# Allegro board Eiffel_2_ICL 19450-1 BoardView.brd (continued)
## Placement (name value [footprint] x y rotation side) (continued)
NOREF#32  -  []  30.94 34.64 90 top
NOREF#33  -  []  176.95 38.55 0 top
NOREF#34  -  []  49.26 27.53 0 top
NOREF#35  -  []  177.55 54.59 90 top
NOREF#36  -  []  225.13 85.49 0 top
NOREF#37  -  [unnamed#2]  3.95 4.39 0 top
NOREF#38  -  []  48.05 24.21 0 top
NOREF#39  -  []  191.47 24.44 0 top
NOREF#40  -  []  181.37 48.8 0 top
NOREF#41  -  []  30.84 37.54 90 top
NOREF#42  -  []  49.95 26.35 0 top
NOREF#43  -  []  169.5 24.9 0 top
NOREF#44  -  []  25.99 59.56 0 top
NOREF#45  -  []  50.6 26.35 90 top
NOREF#46  -  []  229.62 98.92 90 top
NOREF#47  -  []  0 0 0 top
NOREF#48  -  []  186.84 37.95 0 top
NOREF#49  -  []  42.34 37.54 90 top
NOREF#50  *  [unnamed#2]  254.08 109.13 0 top
NOREF#51  -  []  177.55 54.59 90 top
NOREF#52  -  []  176.95 38.55 90 top
NOREF#53  -  []  186.84 37.95 90 top
NOREF#54  -  [unnamed#2]  161.82 65.49 0 top
NOREF#55  -  []  202.97 100.4 0 top
NOREF#56  -  [unnamed#2]  199.27 65.49 0 top
NOREF#57  -  []  49.39 23.54 90 top
NOREF#58  -  []  32.34 39.04 90 top
NOREF#59  -  [unnamed#2]  260.04 100.77 0 top
NOREF#60  -  []  30.84 40.04 0 top
NOREF#61  -  []  176.95 47.79 0 top
NOREF#62  -  []  144.17 28.29 90 top
NOREF#63  -  []  236.87 79.8 90 top
NOREF#64  -  []  0 0 0 top
NOREF#65  -  []  181.37 48.8 90 top
NOREF#66  -  []  178.9 63.83 0 top
NOREF#67  -  []  42.34 40.04 0 top
NOREF#68  -  []  179.5 63.83 90 top
NOREF#69  -  []  51.04 89.5 0 top
NOREF#70  -  []  30.94 34.64 90 top
NOREF#71  -  []  186.84 63.83 0 top
NOREF#72  -  [unnamed#2]  6.13 110.79 0 top
NOREF#73  *  [unnamed#2]  15.9 110.28 0 top
NOREF#74  -  []  213 82.14 0 top
NOREF#75  -  []  179.5 63.83 90 top
NOREF#76  -  []  178.9 59.06 0 top
NOREF#77  -  []  42.44 34.64 90 top
NOREF#78  *  [unnamed#2]  101.6 3.47 0 top
NOREF#79  -  []  37.49 49.55 90 top
NOREF#80  -  []  193.87 23.8 90 top
NOREF#81  -  []  233.4 4.81 90 top
NOREF#82  -  []  174.41 33.37 0 top
NOREF#83  -  []  144.86 28.97 0 top
NOREF#84  *  [unnamed#2]  72.04 97.13 0 top
NOREF#85  -  []  177.55 37.95 90 top
NOREF#86  -  []  186.84 63.83 0 top
NOREF#87  -  []  202.28 99.23 0 top
NOREF#88  *  [unnamed#2]  258.59 96.1 0 top
NOREF#89  -  []  169.5 43.26 90 top
NOREF#90  -  []  0 0 0 top
NOREF#91  -  []  230.79 98.23 90 top
NOREF#92  -  []  210.44 83.44 0 top
NOREF#93  *  [unnamed#2]  125.17 59.05 0 top
NOREF#94  -  []  42.34 40.04 90 top
NOREF#95  -  []  48.7 24.21 90 top
NOREF#96  -  [unnamed#2]  199.27 35.57 0 top
NOREF#97  -  []  260.88 68.29 90 top
NOREF#98  -  []  0 0 0 top
NOREF#99  *  [unnamed#2]  17.39 -5 0 top
NOREF#100  -  [unnamed#2]  8.33 -4.84 0 top
NOREF#101  -  []  228.94 98.23 0 top
NOREF#102  -  []  260.35 49.02 90 top
NOREF#103  -  []  237 7.9 90 top
NOREF#104  -  []  30.84 40.04 90 top
NOREF#105  -  []  176.72 31.77 90 top
NOREF#106  *  [unnamed#2]  24.05 60.57 0 top
NOREF#107  -  []  181.37 48.8 90 top
NOREF#108  -  []  229.62 98.92 0 top
NOREF#109  -  []  25.99 49.55 90 top
NOREF#110  -  []  177.55 53.99 90 top
NOREF#111  *  [unnamed#2]  115.68 39.89 0 top
NOREF#112  -  []  177.55 53.99 90 top
NOREF#113  -  []  32.34 37.04 90 top
NOREF#114  *  [unnamed#2]  3.26 9.13 0 top
NOREF#115  -  []  43.84 37.04 90 top
NOREF#116  -  []  51.04 89 90 top
NOREF#117  -  []  215.38 111.73 0 top
NOREF#118  -  []  43.84 37.04 90 top
NOREF#119  -  []  169.96 24.44 90 top
NOREF#120  -  []  47.36 25.39 0 top
NOREF#121  -  []  43.84 39.04 90 top
NOREF#122  *  [unnamed#2]  69.05 25.48 0 top
NOREF#123  *  [unnamed#2]  32 14.87 180 bottom
NOREF#124  *  [unnamed#2]  17.39 -5 180 bottom
NOREF#125  *  [unnamed#2]  43.91 28.92 180 bottom
NOREF#126  *  [unnamed#2]  254.08 109.13 180 bottom
NOREF#127  *  [unnamed#2]  15.9 110.28 180 bottom
NOREF#128  -  []  260.69 67.28 90 bottom
NOREF#129  *  [unnamed#2]  258.59 96.1 180 bottom
NOREF#130  *  [unnamed#2]  3.26 9.13 180 bottom
NOREF#131  *  [unnamed#2]  72.04 97.13 180 bottom
PC1002  SC22U6D3V3MX-1-GP  [C603H40]  182.89 75.83 270 bottom
PC1003  SC22U6D3V3MX-1-GP  [C603H40]  182.89 77.01 270 bottom
PC1004  SC22U6D3V3MX-1-GP  [C603H40]  176.39 79.15 0 bottom
PC1005  SC22U6D3V3MX-1-GP  [C603H40]  185.79 41.26 270 bottom
PC1006  SC22U6D3V3MX-1-GP  [C603H40]  177.57 79.15 0 bottom
PC1007  SC22U6D3V3MX-1-GP  [C603H40]  178.75 79.15 0 bottom
PC1008  SC22U6D3V3MX-1-GP  [C603H40]  179.93 79.15 0 bottom
PC1009  SC22U6D3V3MX-1-GP  [C603H40]  181.11 79.15 0 bottom
PC1010  SC22U6D3V3MX-1-GP  [C603H40]  182.3 79.15 0 bottom
PC1011  SC22U6D3V3MX-1-GP  [C603H40]  185.38 68.89 270 bottom
PC1012  SC22U6D3V3MX-1-GP  [C603H40]  174.11 41.1 180 bottom
PC1013  SC22U6D3V3MX-1-GP  [C603H40]  172.85 79.15 0 bottom
PC1014  SC22U6D3V3MX-1-GP  [C603H40]  153.54 78.43 180 top
PC1026  SC22U6D3V3MX-1-GP  [C603H40]  182.89 74.65 270 bottom
PC1027  SC22U6D3V3MX-1-GP  [C603H40]  177.95 56.3 90 bottom
PC1028  SC22U6D3V3MX-1-GP  [C603H40]  177.95 57.52 90 bottom
PC1029  SC22U6D3V3MX-1-GP  [C603H40]  152.31 78.43 180 top
PC1030  SC22U6D3V3MX-1-GP  [C603H40]  186.23 40.07 270 bottom
PC1031  SC22U6D3V3MX-1-GP  [C603H40]  174.03 79.15 0 bottom
PC1032  SC22U6D3V3MX-1-GP  [C603H40]  175.21 79.15 0 bottom
PC1042  SC22U6D3V3MX-1-GP  [C603H40]  152.59 58.09 180 top
PC1043  SC22U6D3V3MX-1-GP  [C603H40]  155.76 50.42 0 top
PC1044  SC22U6D3V3MX-1-GP  [C603H40]  156.97 50.42 0 top
PC1045  SC22U6D3V3MX-1-GP  [C603H40]  158.23 50.42 0 top
PC1046  SC22U6D3V3MX-1-GP  [C603H40]  176.56 36.55 270 bottom
PC1047  SC22U6D3V3MX-1-GP  [C603H40]  156.71 56.32 180 top
PC1048  SC22U6D3V3MX-1-GP  [C603H40]  157.88 56.32 180 top
PC1049  SC22U6D3V3MX-1-GP  [C603H40]  177.86 66.55 270 bottom
PC1050  SC22U6D3V3MX-1-GP  [C603H40]  177.85 65.37 270 bottom
PC1051  SC22U6D3V3MX-1-GP  [C603H40]  173.41 68.51 0 bottom
PC1052  SC22U6D3V3MX-1-GP  [C603H40]  174.64 68.52 0 bottom
PC1053  SC22U6D3V3MX-1-GP  [C603H40]  175.82 68.52 0 bottom
PC1054  SC22U6D3V3MX-1-GP  [C603H40]  176.19 62.75 270 bottom
PC1055  SC22U6D3V3MX-1-GP  [C603H40]  153.84 51.99 0 top
PC1056  SC22U6D3V3MX-1-GP  [C603H40]  176.18 61.55 270 bottom
PC1057  SC22U6D3V3MX-1-GP  [C603H40]  174.12 38.43 0 bottom
PC1058  SC22U6D3V3MX-1-GP  [C603H40]  175.79 35.3 270 bottom
PC1059  SC22U6D3V3MX-1-GP  [C603H40]  176.28 54.71 270 bottom
PC4301  SC1U50V3KX-GP  [C603H32]  81 53.69 270 top
PC4302  SCD1U50V3KX-GP  [C603H36]  90.89 51.38 0 bottom
PC4501  SCD1U25V2KX-GP  [C402H22]  112.78 68.17 270 top
PC4502  SC10U25V5KX-GP  [C805H56]  116.18 70.54 90 top
PC4503  SC10U25V5KX-GP  [C805H56]  116.18 68.58 90 top
PC4504  SC10U25V5KX-GP  [C805H56]  112.58 69.75 270 top
PC4505  SCD1U25V2KX-GP  [C402H22]  104.36 71.95 90 bottom
PC4506  SC10U25V5KX-GP  [C805H56]  107.5 70.89 270 bottom
PC4507  SC10U25V5KX-GP  [C805H56]  98.3 71.15 270 top
PC4508  SC10U25V5KX-GP  [C805H56]  101.96 71.7 90 top
PC4509  SC10U25V5KX-GP  [C805H56]  102.9 67.79 90 top
PC4510  SC10U25V5KX-GP  [C805H56]  101.96 69.75 90 top
PC4511  SCD1U25V2KX-GP  [C402H22]  97.84 72.42 0 bottom
PC4512  SCD1U25V2KX-GP  [C402H22]  107.51 75.99 180 top
PC4513  SCD1U25V2KX-GP  [C402H22]  98.82 76.73 0 top
PC4514  SCD1U25V2KX-GP  [C402H22]  102.9 58.14 0 bottom
PC4515  SCD1U25V2KX-GP  [C402H22]  97.59 52.45 90 top
PC4516  SC4D7U6D3V2MX-GP-U  [C402-TO0D2H26]  100.05 79.07 270 top
PC4517  SC4D7U6D3V2MX-GP-U  [C402-TO0D2H26]  102.12 71.91 90 bottom
PC4601  SCD1U25V2KX-GP  [C402H22]  126.04 50.2 270 top
PC4602  SC4D7U6D3V3KX-L-GP  [C603H36]  114.27 44.97 0 top
PC4603  SC2D2U10V3KX-L-GP  [C603H36]  119.55 58.15 180 top
PC4604  SCD1U25V2KX-GP  [C402H22]  121.84 58.51 180 top
PC4605  SCD22U25V3KX-GP  [C603H40]  126.36 53.72 90 top
PC4606  SCD47U25V3KX-1GP  [C603H36]  119.93 44.11 0 top
PC4607  SCD1U25V2KX-GP  [C402H22]  118.51 57.56 180 top
PC4608  SCD1U25V2KX-GP  [C402H22]  127.42 48.63 180 top
PC4609  SCD1U25V2KX-GP  [C402H22]  112.6 54.24 180 top
PC4610  SCD1U25V2KX-GP  [C402H22]  126.03 46.18 270 bottom
PC4611  SCD1U25V2KX-GP  [C402H22]  126.93 49.24 270 bottom
PC4612  SC100P50V2JN-3GP  [C402H22]  124.1 45.54 270 top
PC4613  SC220P50V2KX-3GP  [C402H22]  122.15 45.54 270 top
PC4624  SCD1U25V2KX-L-GP  [C402H22]  112.67 45.89 90 top
PC4701  SC1KP50V2KX-L-1-GP  [C402H22]  150.63 60.17 90 top
PC4702  SC10U25V5KX-L-GP  [C805H56]  132.69 64.69 180 top
PC4703  SC10U25V5KX-L-GP  [C805H56]  132.69 64.69 0 bottom
PC4704  SC10U25V5KX-L-GP  [C805H56]  134.75 64.69 0 bottom
PC4705  SC10U25V5KX-L-GP  [C805H56]  134.76 73.57 0 top
PC4706  SC10U25V5KX-L-GP  [C805H56]  134.76 73.56 180 bottom
PC4707  SC10U25V5KX-L-GP  [C805H56]  132.7 73.57 0 top
PC4708  SC1KP50V2KX-L-1-GP  [C402H22]  150.71 78.31 90 top
PC4709  SC10U25V5KX-L-GP  [C805H56]  134.69 64.69 180 top
PC4710  SC10U25V5KX-L-GP  [C805H56]  132.7 73.57 180 bottom
PC5001  SC1U10V2KX-L1-GP  [C402H22]  143.29 39.01 0 bottom
PC5002  SC1U10V2KX-L1-GP  [C402H22]  144.64 38.39 0 bottom
PC5003  SCD1U25V2KX-GP  [C402H22]  141.66 41.81 0 top
PC5004  SCD1U25V2KX-GP  [C402H22]  145.53 38.39 0 bottom
PC5005  SCD1U25V2KX-GP  [C402H22]  148.72 39.78 0 top
PC5006  SC10U25V5KX-GP  [C805H56]  133.07 51.87 180 bottom
PC5007  SC10U25V5KX-GP  [C805H56]  131.23 51.86 0 top
PC5008  SC10U25V5KX-GP  [C805H56]  133.21 51.86 0 top
PC5010  SC2200P50V2KX-2GP  [C402H22]  152.21 43.55 90 top
PC5011  SC470P50V2KX-3GP  [C402H22]  150.29 43.54 90 top
PC5012  SC22P50V2JN-4GP  [C402H22]  148.85 42.97 180 top
PC5013  SCD1U25V2KX-GP  [C402H22]  152.78 45.94 180 top
PC5101  SCD1U25V2KX-GP  [C402H22]  230.2 84.92 180 bottom
PC5102  SC10U25V5KX-GP  [C805H56]  218.27 85.91 180 bottom
PC5103  SC1U10V2KX-1GP  [C402H22]  237.8 82.03 0 bottom
PC5104  SC1KP50V2KX-1GP  [C402H22]  233.77 96.51 90 bottom
PC5105  SC10U25V5KX-GP  [C805H56]  229.28 89.47 0 bottom
PC5106  SC10U25V5KX-GP  [C805H56]  231.24 89.48 0 bottom
PC5107  SC10U25V5KX-GP  [C805H56]  231.78 84.89 180 bottom
PC5108  SC1U10V2KX-1GP  [C402H22]  224.58 91.08 270 bottom
PC5109  SC1U10V2KX-1GP  [C402H22]  224.58 91.96 270 bottom
PC5110  SCD1U16V2KX-L-GP  [C402H22]  220.52 95.65 270 bottom
PC5111  SCD1U25V2KX-GP  [C402H22]  222.72 86.71 0 bottom
PC5112  SC18P50V2JN-1-GP  [C402H22]  215.88 93.04 0 bottom
PC5113  SCD047U25V2KX-GP  [C402H22]  215.76 91.55 90 bottom
PC5114  SC10U25V5KX-GP  [C805H56]  214.42 90.14 90 bottom
PC5115  SC10U25V5KX-GP  [C805H56]  214.47 87.19 90 bottom
PC5116  SC1U10V2KX-1GP  [C402H22]  217.45 95.48 90 bottom
PC5117  SC22U6D3V3MX-1-GP  [C603H40]  254.18 89.38 90 bottom
PC5118  SC22U6D3V3MX-1-GP  [C603H40]  254.18 88.2 90 bottom
PC5119  SC22U6D3V3MX-1-GP  [C603H40]  254.18 87.03 90 bottom
PC5120  SC22U6D3V3MX-1-GP  [C603H40]  254.19 85.84 90 bottom
PC5121  SC22U6D3V3MX-1-GP  [C603H40]  254.19 84.65 90 bottom
PC5122  SC22U6D3V3MX-1-GP  [C603H40]  254.19 83.47 90 bottom
PC5201  SC22U6D3V3MX-1-GP  [C603H40]  256.28 27.44 90 bottom
PC5202  SC22U6D3V3MX-1-GP  [C603H40]  257.08 17.51 90 bottom
PC5203  SC22U6D3V3MX-1-GP  [C603H40]  257.08 15.55 90 bottom
PC5204  SC100P50V2JN-3GP  [C402H22]  260.12 15.98 270 bottom
PC5205  SCD1U25V2KX-GP  [C402H22]  261.2 30.6 0 bottom
PC5206  SC1U10V2KX-1GP  [C402H22]  259.03 27.5 270 bottom
PC5207  SCD1U16V2KX-3GP  [C402H22]  120.84 18.82 270 bottom
PC5301  SC22U6D3V3MX-1-GP  [C603H40]  126.98 34.24 270 top
PC5302  SC4D7U6D3V3KX-GP  [C603H36]  131.25 38.82 180 top
PC5303  SC22U6D3V3MX-1-GP  [C603H40]  126.98 35.44 270 top
PC5305  SC22U6D3V3MX-1-GP  [C603H40]  127.03 35.45 90 bottom
PC5306  SC22U6D3V3MX-1-GP  [C603H40]  126.98 33.04 90 bottom
PC5307  SC22U6D3V3MX-1-GP  [C603H40]  126.98 34.23 90 bottom
PC5308  SCD1U25V2KX-L-GP  [C402H22]  140.5 39.25 90 top
PC5312  SC220P50V2KX-3GP  [C402H22]  138.04 33.65 180 top
PC5313  SCD01U25V2KX-3GP  [C402H22]  132.43 34.66 0 top
PC5314  SCD1U25V2KX-GP  [C402H22]  134.58 37.08 90 bottom
PC5315  SC10U25V5KX-GP  [C805H56]  139.24 36.99 0 top
PC5316  SC10U25V5KX-GP  [C805H56]  139.24 36.99 180 bottom
PC5320  SCD1U25V2KX-GP  [C402H22]  133.11 39.09 180 bottom
PC5401  SC1U10V2KX-1GP  [C402H22]  122.27 29.78 90 bottom
PC5402  SC10U6D3V3MX-L-GP  [C603H38]  117.16 28.61 0 bottom
PC5403  SC10U6D3V3MX-L-GP  [C603H38]  118.38 28.62 0 bottom
PC5404  SCD1U25V2KX-GP  [C402H22]  117.65 37.95 180 bottom
PC5405  SCD1U25V2KX-GP  [C402H22]  119.12 38.42 90 bottom
PC5406  SCD1U16V2KX-L-GP  [C402H22]  112.9 32.41 270 bottom
PC5407  SCD1U16V2KX-L-GP  [C402H22]  122.58 31.72 90 bottom
PC5410  SC10U6D3V3MX-L-GP  [C603H38]  126.04 37.91 0 bottom
PC5411  SC10U6D3V3MX-L-GP  [C603H38]  111.8 34.85 180 bottom
PC5412  SC10U6D3V3MX-L-GP  [C603H38]  110.63 34.85 180 bottom
PG4501  GAP-CLOSE-PWR-3-GP  [GAP-CLOSE-PWR-3]  105.87 52.38 90 bottom
PG4502  GAP-CLOSE-PWR-3-GP  [GAP-CLOSE-PWR-3]  108.67 52.38 90 bottom
PG4503  GAP-CLOSE-PWR-3-GP  [GAP-CLOSE-PWR-3]  116.43 72 180 top
PG4504  GAP-CLOSE-PWR-3-GP  [GAP-CLOSE-PWR-3]  99.53 67.56 90 bottom
PG4505  GAP-CLOSE-PWR-3-GP  [GAP-CLOSE-PWR-3]  93.28 54.59 180 bottom
PG4506  GAP-CLOSE-PWR-3-GP  [GAP-CLOSE-PWR-3]  93.28 57.44 180 bottom
PG4507  GAP-CLOSE-PWR-3-GP  [GAP-CLOSE-PWR-3]  98.51 67.56 90 bottom
PG4508  GAP-CLOSE-PWR-3-GP  [GAP-CLOSE-PWR-3]  104.02 52.37 90 bottom
PG4509  GAP-CLOSE-PWR-3-GP  [GAP-CLOSE-PWR-3]  106.8 52.38 90 bottom
PG4510  GAP-CLOSE-PWR-3-GP  [GAP-CLOSE-PWR-3]  116.43 72.94 180 top
PG4511  GAP-CLOSE-PWR-3-GP  [GAP-CLOSE-PWR-3]  93.28 55.54 180 bottom
PG4512  GAP-CLOSE-PWR-3-GP  [GAP-CLOSE-PWR-3]  93.27 59.32 180 bottom
PG4513  GAP-CLOSE-PWR-3-GP  [GAP-CLOSE-PWR-3]  103.09 52.37 90 bottom
PG4514  GAP-CLOSE-PWR-3-GP  [GAP-CLOSE-PWR-3]  104.94 52.37 90 bottom
PG4516  GAP-CLOSE-PWR-3-GP  [GAP-CLOSE-PWR-3]  93.28 56.49 180 bottom
PG4517  GAP-CLOSE-PWR-3-GP  [GAP-CLOSE-PWR-3]  93.27 58.38 180 bottom
PG4518  GAP-CLOSE-PWR-3-GP  [GAP-CLOSE-PWR-3]  97.49 67.56 90 bottom
PG4520  GAP-CLOSE-PWR-3-GP  [GAP-CLOSE-PWR-3]  107.74 52.38 90 bottom
PG4529  GAP-CLOSE-PWR-3-GP  [GAP-CLOSE-PWR-3]  102.6 53.59 0 bottom
PG4530  GAP-CLOSE-PWR-3-GP  [GAP-CLOSE-PWR-3]  95.95 59.5 270 bottom
PG4531  GAP-CLOSE-PWR-3-GP  [GAP-CLOSE-PWR-3]  95.02 59.5 270 bottom
PG4532  GAP-CLOSE-PWR-3-GP  [GAP-CLOSE-PWR-3]  100.12 80.02 0 top
PG4533  GAP-CLOSE-PWR-3-GP  [GAP-CLOSE-PWR-3]  101.13 74.38 180 top
PG4601  GAP-CLOSE-PWR-3-GP  [GAP-CLOSE-PWR-3]  109.17 49.71 90 top
PG4701  GAP-CLOSE-PWR-3-GP  [GAP-CLOSE-PWR-3]  148.46 73.29 0 top
PG4702  GAP-CLOSE-PWR-3-GP  [GAP-CLOSE-PWR-3]  131.52 62.15 0 top
PG4703  GAP-CLOSE-PWR-3-GP  [GAP-CLOSE-PWR-3]  131.52 61.24 0 top
PG4704  GAP-CLOSE-PWR-3-GP  [GAP-CLOSE-PWR-3]  131.52 60.33 0 top
PG4705  GAP-CLOSE-PWR-3-GP  [GAP-CLOSE-PWR-3]  131.52 59.41 0 top
PG4706  GAP-CLOSE-PWR-3-GP  [GAP-CLOSE-PWR-3]  146.41 64.49 180 top
PG4707  GAP-CLOSE-PWR-3-GP  [GAP-CLOSE-PWR-3]  148.46 64.49 0 top
PG4708  GAP-CLOSE-PWR-3-GP  [GAP-CLOSE-PWR-3]  131.67 78.56 0 top
PG4709  GAP-CLOSE-PWR-3-GP  [GAP-CLOSE-PWR-3]  131.67 77.65 0 top
PG4710  GAP-CLOSE-PWR-3-GP  [GAP-CLOSE-PWR-3]  131.67 76.73 0 top
PG4711  GAP-CLOSE-PWR-3-GP  [GAP-CLOSE-PWR-3]  131.67 75.82 0 top
PG4712  GAP-CLOSE-PWR-3-GP  [GAP-CLOSE-PWR-3]  146.41 73.28 180 top
PG5001  GAP-CLOSE-PWR-3-GP  [GAP-CLOSE-PWR-3]  129.1 57.93 270 top
PG5002  GAP-CLOSE-PWR-3-GP  [GAP-CLOSE-PWR-3]  128.19 57.93 270 top
PG5003  GAP-CLOSE-PWR-3-GP  [GAP-CLOSE-PWR-3]  130.02 57.93 270 top
PG5004  GAP-CLOSE-PWR-3-GP  [GAP-CLOSE-PWR-3]  130.93 57.93 270 top
PG5005  GAP-CLOSE-PWR-3-GP  [GAP-CLOSE-PWR-3]  146.16 54.45 0 top
PG5006  GAP-CLOSE-PWR-3-GP  [GAP-CLOSE-PWR-3]  148.29 54.43 180 top
PG5101  GAP-CLOSE-PWR-3-GP  [GAP-CLOSE-PWR-3]  227.97 87 0 bottom
PG5102  GAP-CLOSE-PWR-3-GP  [GAP-CLOSE-PWR-3]  227.97 86.07 0 bottom
PG5103  GAP-CLOSE-PWR-3-GP  [GAP-CLOSE-PWR-3]  216.8 85.85 90 bottom
PG5104  GAP-CLOSE-PWR-3-GP  [GAP-CLOSE-PWR-3]  213.36 88.67 0 bottom
PG5201  GAP-CLOSE-PWR-3-GP  [GAP-CLOSE-PWR-3]  259.45 13.53 270 bottom
PG5202  GAP-CLOSE-PWR-3-GP  [GAP-CLOSE-PWR-3]  259.26 34.87 0 bottom
PG5203  GAP-CLOSE-PWR-3-GP  [GAP-CLOSE-PWR-3]  258.43 13.53 270 bottom
PG5204  GAP-CLOSE-PWR-3-GP  [GAP-CLOSE-PWR-3]  259.27 35.79 0 bottom
PG5301  GAP-CLOSE-PWR-3-GP  [GAP-CLOSE-PWR-3]  138.79 42.43 270 top
PG5302  GAP-CLOSE-PWR-3-GP  [GAP-CLOSE-PWR-3]  137.86 42.43 270 top
PG5304  GAP-CLOSE-PWR-3-GP  [GAP-CLOSE-PWR-3]  128.77 32.81 270 top
PG5305  GAP-CLOSE-PWR-3-GP  [GAP-CLOSE-PWR-3]  127.84 32.81 270 top
PG5315  GAP-CLOSE-PWR-3-GP  [GAP-CLOSE-PWR-3]  131.55 32.81 90 top
PG5318  GAP-CLOSE-PWR-3-GP  [GAP-CLOSE-PWR-3]  130.62 32.81 270 top
PG5320  GAP-CLOSE-PWR-3-GP  [GAP-CLOSE-PWR-3]  129.69 32.81 270 top
PG5401  GAP-CLOSE-PWR-3-GP  [GAP-CLOSE-PWR-3]  111.57 37.6 270 bottom
PG5402  GAP-CLOSE-PWR-3-GP  [GAP-CLOSE-PWR-3]  127.13 38.52 270 bottom
PL4501  IND-2D2UH-46-GP-U1  [L7066-1830-UH119]  107.88 57.55 180 top
PL4502  IND-2D2UH-46-GP-U1  [L7066-1830-UH119]  100.25 57.61 0 top
PL4701  COIL-D15UH-2-GP  [L7366-1930H158]  147.43 64.49 90 top
PL4702  COIL-D15UH-2-GP  [L7366-1930H158]  147.43 73.28 90 top
PL5001  COIL-D15UH-2-GP  [L7366-1930H158]  147.24 54.43 90 top
PL5101  COIL-1UH-34-GP-U1  [L7066-1830-UH119]  245.99 88.49 270 bottom
PL5301  COIL-1UH-73-GP  [L4947-1115H119]  127.77 39.68 0 top
PL5401  IND-1UH-382-GP  [L2520-D620H48]  114 38 90 bottom
PL5402  IND-10UH-330-GP  [L2520-D620H48]  123.38 37.49 270 bottom
PR4301  200KR2F-L-GP  [R402H16]  80.89 54.84 90 top
PR4302  20KR2J-L2-GP  [R402H16]  93.06 51.77 0 bottom
PR4303  20KR2J-L2-GP  [R402H16]  92.01 51.78 0 bottom
PR4304  100KR2J-1-GP  [R402H16]  79.89 52.54 270 top
PR4305  D01R2512F-3-GP  [R2512H32]  84.05 49.52 270 top
PR4501  2D2R3-1-U-GP  [R603H22]  104.17 76.06 0 top
PR4502  2D2R3-1-U-GP  [R603H22]  97.63 76.73 180 top
PR4503  118KR2F-1-GP  [R402H16]  104.66 78.98 270 bottom
PR4504  84K5R2F-GP  [R402H16]  98.22 77.83 90 bottom
PR4505  6K8R2F-2-GP  [R402H16]  101.96 79.53 180 bottom
PR4506  15KR2F-GP  [R402H16]  97.23 79.52 270 bottom
PR4507  10KR2F-2-GP  [R402H16]  100.91 79.53 0 bottom
PR4508  10KR2F-2-GP  [R402H16]  99.89 79.53 0 bottom
PR4509  100KR2F-L1-GP  [R402H16]  107.99 72.78 90 bottom
PR4510  100KR2F-L1-GP  [R402H16]  107.99 73.84 90 bottom
PR4511  0R0402-PAD-2-GP  [0R0402-PAD-1]  106.49 73.23 0 bottom
PR4601  26K7R2F-GP  [R402H16]  119.98 41.5 270 top
PR4604  6D2R5F-GP  [R805H24]  115.87 44.52 180 top
PR4605  2D2R3-1-U-GP  [R603H22]  126.36 52.5 90 top
PR4607  10KR2F-L1-GP  [R402H15]  125.39 55.9 270 top
PR4609  2D2R3-1-U-GP  [R603H22]  120.72 58.15 0 top
PR4612  2D2R3-1-U-GP  [R603H22]  122.91 58.9 180 top
PR4613  75R2F-2-GP  [R402H16]  114.07 53.75 270 top
PR4615  3D9R2F-GP  [R402H16]  119.49 46 270 top
PR4616  2D2R3-1-U-GP  [R603H22]  116.33 57.2 180 top
PR4619  3K57R2F-GP  [R402H16]  111.51 46.28 270 bottom
PR4620  1K21R2F-2-GP  [R402H16]  111.4 47.33 90 top
PR4621  9K09R2F-GP  [R402H16]  111.4 48.37 90 top
PR4622  12K4R2F-GP  [R402H16]  116 42.92 180 bottom
PR4624  3K48R2F-GP  [R402H16]  117.47 46.77 180 bottom
PR4625  1K18R2F-GP  [R402H16]  114.33 47.32 90 bottom
PR4626  8K25R2F-1-GP  [R402H16]  114.33 48.36 90 bottom
PR4627  24K9R2F-L-GP  [R402H16]  114.96 42.93 0 bottom
PR4628  2KR3F-L-GP  [R603H22]  127.33 51.27 90 top
PR4629  680R2F-GP  [R402H16]  126.03 48.18 90 top
PR4630  75R2F-2-GP  [R402H16]  114.02 52.56 90 top
PR4631  100R2F-L1-GP-U  [R402H14]  111.5 50.44 270 bottom
PR4632  45D3R2F-L-GP  [R402H16]  111.51 49.4 270 bottom
PR4633  2KR3F-L-GP  [R603H22]  126.42 47.07 90 top
PR4634  0R0402-PAD-2-GP  [0R0402-PAD-1]  114.03 49.41 90 top
PR4635  680R2F-GP  [R402H16]  126.03 48.18 270 bottom
PR4636  0R0402-PAD-2-GP  [0R0402-PAD-1]  114.03 50.46 90 top
PR4637  10KR2F-L1-GP  [R402H15]  112.67 44.82 90 top
PR4638  100R2F-L1-GP-U  [R402H14]  122.15 43.54 90 top
PR4639  NTC-100K-12-GP-U  [NTC-402H22-U]  151.17 68.89 270 top
PR4640  31K6R2F-GP  [R402H16]  124.1 44.58 270 top
PR4641  10KR2F-2-GP  [R402H16]  122.15 44.58 270 top
PR4643  18K7R2F-GP  [R402H16]  120.52 40.83 270 bottom
PR4644  100R2F-L1-GP-U  [R402H14]  122.05 45.32 270 bottom
PR4646  2KR3F-L-GP  [R603H22]  128.51 45.65 90 top
PR4655  2KR3F-L-GP  [R603H22]  129.5 51.75 0 top
PR4659  200R2F-L-GP  [R402H16]  111.98 43.93 90 bottom
PR4660  100R2F-L1-GP-U  [R402H14]  114.33 47.33 90 top
PR4661  100R2F-L1-GP-U  [R402H14]  114.34 48.37 90 top
PR4662  4K64R2F-GP  [R402H16]  126.03 49.23 90 top
PR4663  4K64R2F-GP  [R402H16]  126.03 47.14 270 bottom
PR4665  2K87R2F-1-GP  [R402H16]  118.58 40.88 270 bottom
PR4666  357R2F-GP  [R402H16]  113.47 46.27 270 bottom
PR4667  100R2F-L1-GP-U  [R402H14]  111.41 48.37 90 bottom
PR4668  10R2F-L-GP  [R402H14]  111.41 47.33 90 bottom
PR4669  100R2F-L1-GP-U  [R402H14]  116.01 45.1 180 bottom
PR4671  0R0402-PAD-1-GP  [0R0402-PAD]  122.15 42.49 90 top
PR4672  0R0402-PAD-1-GP  [0R0402-PAD]  122.04 44.28 270 bottom
PR4674  0R0402-PAD-1-GP  [0R0402-PAD]  114.02 51.49 90 top
PR4677  0R0402-PAD-1-GP  [0R0402-PAD]  118.83 44.5 0 top
PR4688  0R0402-PAD-1-GP  [0R0402-PAD]  112.67 43.78 90 top
PR4701  110KR2F-GP  [R402H16]  130.37 68.65 90 bottom
PR4702  NTC-100K-12-GP-U  [NTC-402H22-U]  130.37 69.69 90 bottom
PR4704  2D2R6J-3-GP  [R1206H28]  147.35 59.51 90 top
PR4705  2D2R6J-3-GP  [R1206H28]  147.35 78.31 90 top
PR5001  5D1R3J-GP  [R603H22]  140.92 34.62 270 top
PR5002  0R0402-PAD-1-GP  [0R0402-PAD]  141.85 35.9 90 top
PR5003  100KR2F-L1-GP  [R402H16]  150.27 41.72 90 top
PR5004  715KR2F-GP  [R402H18]  149.47 35.89 180 top
PR5005  100KR2F-L1-GP  [R402H16]  144.3 44.42 180 top
PR5006  100KR2F-L1-GP  [R402H16]  143.23 44.42 180 top
PR5007  2D2R3-1-U-GP  [R603H22]  141.23 44.75 270 top
PR5008  17K8R2F-GP  [R402H16]  149.08 37.41 90 top
PR5009  1R2J-GP  [R402H16]  150.18 39.81 90 top
PR5010  1R2J-GP  [R402H16]  148.95 39.4 90 bottom
PR5011  NTC-10K-29-GP-U  [NTC-402H22-U]  148.3 50.03 270 top
PR5012  0R0402-PAD-1-GP  [0R0402-PAD]  145.37 44.92 180 top
PR5013  10KR2F-2-GP  [R402H16]  147.9 43.75 0 top
PR5014  3K4R2F-GP  [R402H16]  150.27 45.61 270 top
PR5015  5K62R2F-GP  [R402H16]  146.87 43.75 180 top
PR5016  0R0402-PAD-1-GP  [0R0402-PAD]  150.28 46.7 90 top
PR5017  100R2F-L1-GP-U  [R402H14]  152.82 47.47 270 top
PR5018  100R2F-L1-GP-U  [R402H14]  147.1 46.71 180 top
PR5033  1R3J-L1-GP  [R603H22]  146.78 35.26 0 top
PR5034  0R0402-PAD-1-GP  [0R0402-PAD]  143.43 35.66 180 top
PR5035  0R0402-PAD-1-GP  [0R0402-PAD]  144.52 35.66 180 top
PR5052  0R0402-PAD-1-GP  [0R0402-PAD]  145.62 35.66 180 top
PR5105  2D2R5J-1-GP  [R805H24]  237.11 97.04 90 bottom
PR5106  191KR2F-1-GP  [R402H16]  225.1 89.29 270 bottom
PR5108  5D1R2F-GP  [R402H16]  225.07 93.37 0 bottom
PR5109  2D2R3-1-U-GP  [R603H22]  222.61 94.86 270 top
PR5110  100KR2J-1-GP  [R402H16]  224.01 94.85 180 bottom
PR5111  750KR2F-GP  [R402H16]  218.49 94.49 90 top
PR5113  0R0402-PAD-2-GP  [0R0402-PAD-1]  220.47 97.06 180 bottom
PR5114  0R0402-PAD-2-GP  [0R0402-PAD-1]  218.96 95.41 180 bottom
PR5115  2D2R5J-1-GP  [R805H24]  221.68 84.68 270 bottom
PR5116  20KR2F-L-GP  [R402H16]  216.65 94.52 90 bottom
PR5117  15K8R2F-GP  [R402H16]  216.85 93.05 0 bottom
PR5120  0R0402-PAD-1-GP  [0R0402-PAD]  254.32 90.49 90 bottom
PR5201  10KR2F-2-GP  [R402H16]  260.77 17.96 270 bottom
PR5202  100KR2F-L1-GP  [R402H16]  260.61 27.67 180 bottom
PR5203  21K5R2F-GP  [R402H16]  260.12 16.94 270 bottom
PR5204  100KR2J-1-GP  [R402H16]  260.25 30.61 180 bottom
PR5301  82KR2F-1-GP  [R402H16]  139.07 33.65 180 top
PR5302  12K7R2F-GP  [R402H16]  137.07 33.76 180 top
PR5303  100KR2F-L3-GP  [R402H16]  134.56 38.03 90 bottom
PR5304  10KR2F-L1-GP  [R402H15]  136.65 33.72 90 bottom
PR5317  0R0402-PAD-2-GP  [0R0402-PAD-1]  134.5 32.05 270 top
PR5325  1KR2J-1-GP  [R402H16]  134.46 32.68 270 bottom
PR5326  0R0402-PAD-2-GP  [0R0402-PAD-1]  134.98 33.86 180 top
PR5327  100KR2F-L1-GP  [R402H16]  133.4 33.71 180 top
PR5331  1KR2J-1-GP  [R402H16]  136.02 33.81 180 top
PR5401  0R0402-PAD-2-GP  [0R0402-PAD-1]  116.68 37.95 180 bottom
PR5402  -  [0R0402-PAD]  113.35 34.48 90 bottom
PR5403  -  [0R0402-PAD]  123.49 34.22 270 bottom
PR5405  -  [0R0402-PAD]  114.32 30.29 90 bottom
PR5407  10KR2F-2-GP  [R402H16]  121.98 34.23 180 bottom
PR5408  7K5R2F-1-GP  [R402H16]  123.48 35.31 90 bottom
PR5410  0R0402-PAD-1-GP  [0R0402-PAD]  119.53 29.01 0 bottom
PR5413  0R0402-PAD-2-GP  [0R0402-PAD-1]  122.27 28.82 90 bottom
PR5419  0R0402-PAD-1-GP  [0R0402-PAD]  113.35 35.53 90 bottom
PR5420  100KR2J-1-GP  [R402H16]  112.89 31.46 270 bottom
PR5421  100KR2J-1-GP  [R402H16]  122.56 30.77 90 bottom
PR5422  0R0402-PAD-1-GP  [0R0402-PAD]  116.04 29.01 0 bottom
PR5423  0R0402-PAD-2-GP  [0R0402-PAD-1]  119.76 37.03 180 bottom
PT4501  ST150U6D3VDK-GP  [CT7343H83]  107.18 58.13 0 bottom
PT4502  SE220U6D3VM-8GP  [SE331721H237]  91.73 55.89 270 top
PT4701  SE330U2D5VDM-2GP  [CT7343H83]  149.61 70.8 180 bottom
PT4703  ST33U25VDM-5-GP  [CT7343H79]  126.39 66.04 270 top
PT5001  SE330U2D5VDM-2GP  [CT7343H83]  150.78 53.28 180 bottom
PT5002  ST33U25VDM-5-GP  [CT7343H79]  126.39 72.47 270 top
PU4301  SM4305PSKC-TRG-GP  [SOIC8H69]  87.47 56 0 bottom
PU4501  SM3434NSQAC-TRG-GP  [PPAK-8P-3333-2H40]  115.67 61.57 270 top
PU4502  SM3434NSQAC-TRG-GP  [PPAK-8P-3333-2H40]  98.83 65.71 0 top
PU4503  RT6575DGQW-GP  [QFN20-G1D75H32]  102.59 75.87 180 bottom
PU4504  SM3432NSQAC-TRG-GP  [PPAK-8P-3333-1H40]  110.11 64.19 180 top
PU4505  SM3432NSQAC-TRG-GP  [PPAK-8P-3333-1H40]  103.17 64.54 90 top
PU4601  RT3612EBGQW-1-GP  [QFN32J4-G2D75H32]  120.14 50.5 90 top
PU4701  FDMS3600-02-RJK0215-COLAY-GP  [PPAK-8P-G5324H44-COLAY]  138.91 64.08 0 top
PU4702  FDMS3600-02-RJK0215-COLAY-GP  [PPAK-8P-G5324H44-COLAY]  138.91 64.08 180 bottom
PU4703  FDMS3600-02-RJK0215-COLAY-GP  [PPAK-8P-G5324H44-COLAY]  138.91 73.94 0 bottom
PU4704  FDMS3600-02-RJK0215-COLAY-GP  [PPAK-8P-G5324H44-COLAY]  138.91 73.94 180 top
PU5001  RT6543AGQW-GP  [QFN20-G1D75H32]  144.86 40.22 270 top
PU5002  PK600BA-GP  [PPAK-5PH48]  137.24 55.07 90 top
PU5003  PK6B0SA-GP  [PPAK-5PH48]  139.27 48.67 270 top
PU5004  PK6B0SA-GP  [PPAK-5PH48]  139.27 48.67 90 bottom
PU5005  PK600BA-GP  [PPAK-5PH48]  137.25 55.02 270 bottom
PU5101  SM4378NSKPC-TRG-GP  [PPAK-8PH48]  235.8 86.54 270 bottom
PU5102  SM4504NHKPC-TRG-1-GP  [PPAK-8PH48]  237.81 92.88 90 bottom
PU5103  RT8231AGQW-GP  [QFN20-G1D75H32]  220.51 90.8 270 bottom
PU5201  APL5930KAI-TRG-1-GP  [SOIC8-G3530H63]  258.91 22.55 180 bottom
PU5301  G5335DQZ1U-GP  [QFN22G4-G2P-1H36]  135.19 38.63 180 top
PU5401  APW8738AQBI-TRG-1-GP  [QFN16G3-G2H34]  117.99 33.45 180 bottom
PWRBT1  SW-TACT-4P-278-GP  [TA2-32N-Q-T-R]  124.5 3.2 180 bottom
Q1801  2N7002KDW-1-GP  [SOT-363H44]  173.7 7.39 180 top
Q1820  2N7002K-2-GP  [SOT23DGS2D4H44]  206.87 16.95 180 bottom
Q1901  PMBS3906-GP  [SOT-23-10H44]  211.07 7.98 180 bottom
Q1904  PJT138KA-GP  [SOT-363H44]  201.85 15.39 90 bottom
Q2401  2N7002K-2-GP  [SOT23DGS2D4H44]  85.32 28.54 0 bottom
Q2402  2N7002K-2-GP  [SOT23DGS2D4H44]  70.15 8.53 90 top
Q2403  2N7002KDW-1-GP  [SOT-363H44]  72.84 18.61 0 bottom
Q2404  2N7002K-2-GP  [SOT23DGS2D4H44]  88.9 28.54 180 bottom
Q2501  2N7002K-2-GP  [SOT23DGS2D4H44]  163.57 14.92 180 bottom
Q3111  2N7002K-2-GP  [SOT23DGS2D4H44]  68.63 83.75 0 top
Q3401  2N7002KDW-1-GP  [SOT-363H44]  34.29 54.94 90 bottom
Q3402  2N7002K-2-GP  [SOT23DGS2D4H44]  38.14 56.72 270 bottom
Q4001  2N7002KDW-1-GP  [SOT-363H44]  131.52 44.84 90 bottom
Q4004  2N7002KDW-1-GP  [SOT-363H44]  146.47 31.85 270 top
Q4006  MMDT3904-2-GP  [SOT-363-1H44]  199.41 77.62 180 top
Q4007  2N7002K-2-GP  [SOT23DGS2D4H44]  129.95 24.71 90 bottom
Q4009  MMDT3904-2-GP  [SOT-363-1H44]  128.09 21.27 90 bottom
Q4012  MMDT3904-2-GP  [SOT-363-1H44]  218.2 6.37 270 bottom
Q4013  LMBT3904LT1G-GP  [SOT23CBE2D4H44]  218.94 9.82 180 bottom
Q4301  2N7002K-2-GP  [SOT23DGS2D4H44]  114.66 57.45 90 bottom
Q4308  2N7002K-2-GP  [SOT23DGS2D4H44]  82.8 52.71 180 bottom
Q5506  PA010BV-GP  [SOIC8H75]  13.39 15.57 180 top
Q5701  2N7002KDW-1-GP  [SOT-363H44]  41.61 56.69 0 bottom
Q5702  2N7002K-2-GP  [SOT23DGS2D4H44]  67.57 17.83 90 top
Q5705  2N7002K-2-GP  [SOT23DGS2D4H44]  51.05 53.68 0 bottom
Q6401  PMBS3906-GP  [SOT-23-10H44]  119.29 11.18 180 top
Q6402  NX7002BK-GP  [SOT23DGS2D4H44]  122.94 11.83 180 top
Q6801  PJA3413-1-GP  [SOT23DGS2D4H44]  13.76 92.93 90 top
Q6803  PJA3413-1-GP  [SOT23DGS2D4H44]  13.73 89.34 90 top
Q6805  2N7002K-2-GP  [SOT23DGS2D4H44]  13.64 85.76 90 top
R301  51R2J-L1-GP  [R402H16]  160.97 70.76 0 top
R302  1KR2F-3-GP  [R402H16]  161.65 74.13 90 top
R306  1KR2F-3-GP  [R402H16]  169.06 72.62 0 bottom
R309  49D9R2F-GP  [R402H16]  190.44 38.01 90 bottom
R310  49D9R2F-GP  [R402H16]  164.81 24.19 90 top
R311  100R2F-L1-GP-U  [R402H14]  168.62 71.17 90 bottom
R312  49D9R2F-GP  [R402H16]  171.56 72.24 180 bottom
R313  51R2J-L1-GP  [R402H16]  163.67 70.19 90 top
R325  0R2J-2-GP  [R402H16]  113.59 54.33 0 bottom
R401  150R2F-1-GP  [R402H16]  159.92 70.76 0 top
R402  150R2F-4-L-GP  [R402H16]  165.79 50.25 270 top
R403  100KR2J-1-GP  [R402H16]  163.67 71.23 90 top
R505  100R2F-L1-GP-U  [R402H14]  195.57 76.99 0 top
R506  100R2F-L1-GP-U  [R402H14]  193.39 76.99 0 top
R507  100R2F-L1-GP-U  [R402H14]  194.49 77 0 top
R510  470R2F-GP  [R402H16]  209.8 16.97 180 bottom
R511  0R0402-PAD-2-GP  [0R0402-PAD-1]  211.27 16.53 90 bottom
R605  49D9R2F-GP  [R402H16]  170.51 61.34 180 bottom
R606  100R2F-L1-GP-U  [R402H14]  169.46 61.35 0 bottom
R607  1KR2J-L2-GP  [R402H15]  168.18 60.03 180 bottom
R702  43R2F-2-GP  [R402H15]  111.51 49.4 90 top
R704  100R2F-L1-GP-U  [R402H14]  177.02 71.53 180 bottom
R705  100R2F-L1-GP-U  [R402H14]  178.07 71.54 180 bottom
R706  0R0402-PAD-2-GP  [0R0402-PAD-1]  111.84 52.04 0 top
R707  56R2J-4-GP  [R402H16]  111.52 50.57 90 top
R708  100R2F-L1-GP-U  [R402H14]  111.5 51.47 270 bottom
R808  0R0603-PAD-2-GP-U  [0R0603-PAD-1-U]  183.52 64.99 90 bottom
R809  0R0402-PAD-2-GP  [0R0402-PAD-1]  170.51 72.25 0 bottom
R1214  2R2F-GP  [R402H16]  256.07 35.69 270 bottom
R1215  24D9R2F-L-GP  [R402H16]  256.17 38.85 270 bottom
R1231  240R2F-1-GP  [R402H16]  256.75 44.43 270 bottom
R1302  0R0402-PAD-2-GP  [0R0402-PAD-1]  241.75 8.79 0 bottom
R1303  240R2F-1-GP  [R402H16]  241.56 42.8 180 bottom
R1305  2R2F-GP  [R402H16]  242.11 34.57 270 bottom
R1306  24D9R2F-L-GP  [R402H16]  244.05 31.32 270 bottom
R1501  4K7R2J-L-GP  [R402H15]  169.27 18.21 270 bottom
R1502  20K5R2F-GP  [R402H16]  169.25 17.1 90 bottom
R1503  100KR2J-1-GP  [R402H16]  194.31 14.23 0 top
R1504  100KR2J-1-GP  [R402H16]  177.33 16.63 180 top
R1505  4K7R2J-L-GP  [R402H15]  209.38 19.16 0 bottom
R1506  100KR2J-1-GP  [R402H16]  199.92 9.51 270 bottom
R1507  100KR2J-1-GP  [R402H16]  185.99 19.16 90 top
R1508  4K7R2J-L-GP  [R402H15]  185.38 20.75 0 bottom
R1510  0R0402-PAD-2-GP  [0R0402-PAD-1]  192.57 11.76 270 top
R1511  4K7R2J-L-GP  [R402H15]  193.25 14.24 180 top
R1512  4K7R2J-L-GP  [R402H15]  176.27 16.63 0 top
R1513  20K5R2F-GP  [R402H16]  209.81 20.63 270 bottom
R1514  4K7R2J-L-GP  [R402H15]  200.96 10.55 270 bottom
R1516  4K7R2J-L-GP  [R402H15]  186.72 20.22 90 top
R1517  20K5R2F-GP  [R402H16]  184.34 20.83 180 bottom
R1518  2K2R2J-2-GP  [R402H16]  204.55 24.22 180 top
R1519  2K2R2J-2-GP  [R402H16]  187.43 20.82 0 bottom
R1520  4K7R2J-L-GP  [R402H15]  212.26 19.15 0 bottom
R1521  20K5R2F-GP  [R402H16]  211.79 20.64 90 bottom
R1522  4K7R2J-L-GP  [R402H15]  168.97 22.02 270 bottom
R1523  20K5R2F-GP  [R402H16]  168.98 23.1 90 bottom
R1524  4K7R2J-L-GP  [R402H15]  177.49 20.25 90 top
R1525  20K5R2F-GP  [R402H16]  178.5 21.28 90 top
R1526  4K7R2J-L-GP  [R402H15]  186.4 20.75 0 bottom
R1527  20K5R2F-GP  [R402H16]  187.35 27.22 180 bottom
R1528  4K7R2J-L-GP  [R402H15]  199.65 30.57 90 bottom
R1529  20K5R2F-GP  [R402H16]  192.82 32.38 180 bottom
R1530  4K7R2J-L-GP  [R402H15]  184.76 20.19 270 top
R1531  100KR2J-1-GP  [R402H16]  193.19 7.17 180 top
R1532  10KR2J-3-GP  [R402H16]  182.65 29.36 0 bottom
R1533  2K2R2J-2-GP  [R402H16]  179.81 30.62 0 bottom
R1534  100KR2J-1-GP  [R402H16]  192.16 7.16 0 top
R1601  100R2F-L1-GP-U  [R402H14]  165.72 27.36 180 top
R1602  10KR2J-L-GP  [R402H15]  175.34 25.52 180 bottom
R1603  113R2F-GP  [R402H16]  165.76 29.01 270 top
R1604  10KR2J-L-GP  [R402H15]  164.68 27.37 180 top
R1605  10KR2J-L-GP  [R402H15]  206.44 23.76 0 top
R1606  10KR2J-L-GP  [R402H15]  183.65 16.65 0 bottom
R1608  10KR2J-3-GP  [R402H16]  187.7 30.99 90 bottom
R1701  1KR2F-3-GP  [R402H16]  171.7 22.21 0 bottom
R1704  1MR2F-GP  [R402H16]  192.26 19.31 0 bottom
R1705  4K7R2J-L-GP  [R402H15]  198.85 20.71 90 top
R1706  100KR2J-1-GP  [R402H16]  198.85 21.73 270 top
R1709  0R0402-PAD-2-GP  [0R0402-PAD-1]  201.2 24.83 270 top
R1712  100KR2J-1-GP  [R402H16]  184.73 13.98 270 bottom
R1713  100KR2J-1-GP  [R402H16]  199.63 29.52 90 bottom
R1714  10KR2J-3-GP  [R402H16]  202.42 18.03 270 top
R1715  10KR2J-3-GP  [R402H16]  198.1 25.25 90 top
R1716  10KR2J-3-GP  [R402H16]  191.13 20.81 180 bottom
R1717  10KR2J-3-GP  [R402H16]  201.12 29.95 180 bottom
R1718  100KR2J-1-GP  [R402H16]  207.46 20.93 0 bottom
R1720  0R0402-PAD-2-GP  [0R0402-PAD-1]  190.09 20.81 0 bottom
R1722  0R0402-PAD-2-GP  [0R0402-PAD-1]  199.69 23.77 0 top
R1726  100KR2J-1-GP  [R402H16]  201.17 23.77 90 top
R1727  0R0402-PAD-2-GP  [0R0402-PAD-1]  200.76 20.97 90 top
R1728  100KR2J-1-GP  [R402H16]  199.58 25.91 0 top
R1729  100KR2J-1-GP  [R402H16]  190.29 25.07 270 bottom
R1730  10KR2J-3-GP  [R402H16]  176.36 13.16 0 top
R1732  10KR2J-3-GP  [R402H16]  185.17 34.31 180 bottom
R1746  10KR2J-3-GP  [R402H16]  192.44 24.64 270 bottom
R1804  51R2J-2-GP  [R402H16]  103.15 6.17 180 bottom
R1805  51R2J-2-GP  [R402H16]  103.13 8.82 0 bottom
R1811  10MR2J-L-GP  [R402H16]  195.37 24.01 90 bottom
R1812  10KR2J-3-GP  [R402H16]  189.24 20.83 180 top
R1813  10KR2J-3-GP  [R402H16]  188.21 20.83 180 top
R1818  75KR2F-GP  [R402H16]  192.77 36.4 0 bottom
R1819  60D4R2F-GP  [R402H16]  164.8 23.08 270 top
R1820  200KR2F-L-GP  [R402H16]  172.48 19.2 270 top
R1821  100KR2F-L1-GP  [R402H16]  210.41 14.98 180 bottom
R1823  51R2J-2-GP  [R402H16]  192.58 9.69 270 top
R1824  51R2J-2-GP  [R402H16]  201.82 9.5 90 bottom
R1825  51R2J-2-GP  [R402H16]  192.58 10.72 270 top
R1826  51R2J-2-GP  [R402H16]  194.23 7.19 180 top
R1827  51R2J-2-GP  [R402H16]  199.42 16.76 180 top
R1833  2K2R2J-2-GP  [R402H16]  204.56 16.5 0 bottom
R1839  100KR2J-4-GP  [R402H15]  191.59 34.47 180 bottom
R1840  100KR2J-1-GP  [R402H16]  192.68 26.99 0 bottom
R1841  100KR2J-1-GP  [R402H16]  176.87 6.8 180 bottom
R1842  100KR2J-1-GP  [R402H16]  199.51 28.05 0 bottom
R1843  100KR2J-1-GP  [R402H16]  178.46 25.03 0 bottom
R1844  100KR2J-1-GP  [R402H16]  176.81 25.1 270 bottom
R1901  33R2J-L1-GP  [R402H15]  205.54 26.13 180 top
R1902  200R2F-L-GP  [R402H16]  192.34 38.82 270 bottom
R1903  200R2F-L-GP  [R402H16]  188.19 35.65 0 bottom
R1904  33R2J-L1-GP  [R402H15]  204.69 19.64 180 top
R1905  33R2J-L1-GP  [R402H15]  204.6 21.59 180 top
R1912  33R2F-3-GP  [R402H16]  206.4 28.53 180 top
R1913  33R2F-3-GP  [R402H16]  207.61 22.95 270 bottom
R1914  1KR2J-1-GP  [R402H16]  213.39 6.87 0 bottom
R1915  1KR2J-1-GP  [R402H16]  210.26 4.05 270 bottom
R1916  0R2J-2-GP  [R402H16]  87.05 23.73 180 bottom
R1919  33R2J-L1-GP  [R402H15]  204.32 18.03 270 top
R1920  0R2J-2-GP  [R402H16]  98.39 7.44 90 top
R2001  49K9R2F-L-LS-GP  [R402H16]  180.46 16.06 180 top
R2002  49K9R2F-L-LS-GP  [R402H16]  181.54 16.05 180 top
R2003  10KR2F-L1-GP  [R402H15]  210.42 19.16 180 bottom
R2021  10KR2J-L-GP  [R402H15]  178.37 16.65 180 top
R2023  10KR2J-L-GP  [R402H15]  176.61 21.29 270 top
R2031  10KR2F-2-GP  [R402H16]  184.09 16.49 270 top
R2041  10KR2F-2-GP  [R402H16]  182.6 16.05 0 top
R2101  200R2F-L-GP  [R402H16]  183.59 25.45 0 bottom
R2102  150R2F-1-GP  [R402H16]  191.93 22.77 90 bottom
R2103  100R2F-L1-GP-U  [R402H14]  173.17 72.29 0 bottom
R2104  20KR2F-L-GP  [R402H16]  181.51 20.81 0 top
R2105  20KR2F-L-GP  [R402H16]  182.54 20.81 0 top
R2106  49D9R2F-GP  [R402H16]  186.72 21.27 270 top
R2107  49D9R2F-GP  [R402H16]  184 21.25 90 top
R2108  100KR2J-1-GP  [R402H16]  179.29 12.81 0 bottom
R2201  100KR2J-1-GP  [R402H16]  184.13 34.31 180 bottom
R2204  0R0402-PAD-2-GP  [0R0402-PAD-1]  171.77 26.15 180 bottom
R2206  D1R2F-1-GP  [R402H16]  172.85 25.13 180 bottom
R2208  0R0402-PAD-2-GP  [0R0402-PAD-1]  185.27 32.85 270 bottom
R2209  100KR2J-1-GP  [R402H16]  177.21 28.91 180 bottom
R2210  100KR2J-1-GP  [R402H16]  187.2 33.67 270 bottom
R2508  3K3R2F-2-GP  [R402H16]  197.95 17.18 90 top
R2510  1KR2F-3-GP  [R402H16]  165.1 9.21 90 bottom
R2511  1MR2J-1-GP  [R402H16]  166.05 8.18 270 bottom
R2514  45K3R2F-L-GP  [R402H16]  168.53 8.8 180 bottom
R2519  0R0402-PAD-2-GP  [0R0402-PAD-1]  169.57 8.8 180 bottom
R2531  4K7R2J-2-GP  [R402H16]  260.21 26.41 0 top
R2601  0R2J-2-GP  [R402H16]  258.83 8.91 180 bottom
R2602  22KR2J-GP  [R402H16]  258.42 2.93 0 bottom
R2603  2K2R2J-2-GP  [R402H16]  259.45 2.92 0 bottom
R2604  0R2J-2-GP  [R402H16]  258.87 6.76 270 bottom
R2605  0R0402-PAD-2-GP  [0R0402-PAD-1]  259.47 5.28 0 bottom
R2606  4K7R2J-2-GP  [R402H16]  260.18 14.59 0 top
R2607  8K2R2F-1-GP  [R402H16]  259.13 14.6 180 top
R2701  0R2J-2-GP  [R402H16]  25.53 67.36 180 bottom
R2702  0R0402-PAD-2-GP  [0R0402-PAD-1]  34.58 74.34 0 bottom
R2703  0R0402-PAD-2-GP  [0R0402-PAD-1]  33.55 74.34 0 bottom
R2704  0R0402-PAD-2-GP  [0R0402-PAD-1]  29.63 74.34 0 bottom
R2705  0R0402-PAD-2-GP  [0R0402-PAD-1]  29.22 68.18 180 bottom
R2706  0R0402-PAD-2-GP  [0R0402-PAD-1]  30.66 74.34 0 bottom
R2709  100KR2F-L3-GP  [R402H16]  36.57 77.29 90 top
R2710  0R0402-PAD-2-GP  [0R0402-PAD-1]  32.49 78.73 180 top
R2711  100KR2F-L3-GP  [R402H16]  26.67 76.2 270 top
R2712  0R2J-2-GP  [R402H16]  31.34 78.73 180 top
R2713  200KR2F-L-3-GP  [R402H16]  36.59 78.35 90 top
R2714  0R0603-PAD-2-GP-U  [0R0603-PAD-1-U]  37.34 65.68 180 top
R2718  33R2J-L1-GP  [R402H15]  38.48 73.91 270 top
R2721  0R0402-PAD-2-GP  [0R0402-PAD-1]  24.48 67.32 180 bottom
R2722  0R0402-PAD-2-GP  [0R0402-PAD-1]  38.43 73.98 270 bottom
R2723  2K2R2J-2-GP  [R402H16]  34.02 78.53 90 top
R2730  10KR2F-L1-GP  [R402H15]  38.49 75.98 90 top
R2731  0R2J-2-GP  [R402H16]  38.61 78.94 90 top
R2732  0R0402-PAD-2-GP  [0R0402-PAD-1]  38.33 75.07 270 bottom
R2733  0R0402-PAD-2-GP  [0R0402-PAD-1]  33.66 77.05 180 top
R2754  0R0402-PAD-2-GP  [0R0402-PAD-1]  36.94 67.8 90 bottom
R2755  0R0603-PAD-1-GP-U  [0R0603-PAD-U]  37.66 77.46 270 bottom
R2758  0R0603-PAD-2-GP-U  [0R0603-PAD-1-U]  42.89 67.78 180 top
R2759  0R3J-0-U-GP  [R603H22]  42.89 70.47 0 top
R2766  0R0402-PAD-2-GP  [0R0402-PAD-1]  26.37 65.47 180 bottom
R2767  0R2J-2-GP  [R402H16]  27.39 65.47 0 bottom
R2768  0R0603-PAD-2-GP-U  [0R0603-PAD-1-U]  42.8 63.89 180 top
R2769  0R3J-0-U-GP  [R603H22]  43.56 65.85 270 top
R2778  47KR2J-L2-GP  [R402H15]  38.48 74.94 90 top
R2902  -  [0R0402-PAD]  15.38 49.43 90 top
R2904  75R2J-1-GP  [R402H16]  24.76 70.68 270 top
R2905  75R2J-1-GP  [R402H16]  24.84 69.62 270 top
R2909  0R0402-PAD-2-GP  [0R0402-PAD-1]  16.46 51.49 0 top
R2922  0R0402-PAD-2-GP  [0R0402-PAD-1]  21.42 74.65 90 top
R2923  0R0402-PAD-2-GP  [0R0402-PAD-1]  22.5 64.53 90 top
R2924  0R0402-PAD-2-GP  [0R0402-PAD-1]  23.12 77.85 45 top
R3001  0R2J-2-GP  [R402H16]  224.11 96.38 90 top
R3002  0R2J-2-GP  [R402H16]  226.02 96.38 90 top
R3003  33R2J-L1-GP  [R402H15]  224.91 95.36 90 top
R3004  33R2J-L1-GP  [R402H15]  227.47 95.96 0 top
R3005  0R3J-0-U-GP  [R603H22]  219.36 97.8 0 bottom
R3006  0R0603-PAD-2-GP-U  [0R0603-PAD-1-U]  226.86 100.29 90 bottom
R3008  0R0603-PAD-2-GP-U  [0R0603-PAD-1-U]  218.17 98.15 0 bottom
R3102  2K49R2F-GP  [R402H16]  66.51 80.61 0 bottom
R3103  0R0805-PAD-2-GP-U  [0R0805-PAD-1-U]  69.36 85.39 270 bottom
R3106  1KR2J-1-GP  [R402H16]  57.94 74.53 270 top
R3107  0R5J-5-GP  [R805H24]  56.95 81.39 90 top
R3114  0R2J-2-GP  [R402H16]  61.19 89.41 270 top
R3115  0R0402-PAD-2-GP  [0R0402-PAD-1]  61.19 90.42 270 top
R3116  10KR2J-3-GP  [R402H16]  59.58 71.46 90 top
R3121  10MR2J-L-GP  [R402H16]  67.84 82.89 180 bottom
R3135  0R0603-PAD-2-GP-U  [0R0603-PAD-1-U]  66.89 89.89 180 top
R3136  510R2J-1-GP  [R402H16]  68.91 86.19 90 top
R3138  330R2J-3-GP  [R402H16]  58.2 70.74 90 bottom
R3139  330R2J-3-GP  [R402H16]  54 63.37 0 bottom
R3141  0R0402-PAD-2-GP  [0R0402-PAD-1]  68.37 80.37 180 top
R3142  0R0402-PAD-2-GP  [0R0402-PAD-1]  64.76 89.89 0 top
R3143  10KR2J-3-GP  [R402H16]  57.79 82.14 270 bottom
R3144  10KR2J-3-GP  [R402H16]  65.79 89.89 180 top
R3150  1K5R2F-2-GP  [R402H16]  67.84 81 0 bottom
R3151  249R2F-GP  [R402H16]  52.96 63.37 0 bottom
R3152  249R2F-GP  [R402H16]  58.21 71.78 90 bottom
R3154  0R0402-PAD-2-GP  [0R0402-PAD-1]  55.37 60.77 0 bottom
R3156  75R3J-L-GP  [R603H22]  59.79 58.74 90 bottom
R3157  75R3J-L-GP  [R603H22]  59.8 55.16 90 bottom
R3158  75R3J-L-GP  [R603H22]  59.8 56.35 90 bottom
R3159  75R3J-L-GP  [R603H22]  59.79 57.55 90 bottom
R3160  1KR2J-1-GP  [R402H16]  63.71 89.76 0 top
R3161  15KR2F-GP  [R402H16]  62.68 89.75 180 top
R3301  6K2R2F-GP  [R402H16]  40.58 92.46 90 bottom
R3302  0R0603-PAD-2-GP-U  [0R0603-PAD-1-U]  33.29 84.43 90 bottom
R3303  0R0402-PAD-2-GP  [0R0402-PAD-1]  23.75 91.44 180 bottom
R3304  0R0402-PAD-2-GP  [0R0402-PAD-1]  22.61 91.44 180 bottom
R3305  0R0402-PAD-2-GP  [0R0402-PAD-1]  28.08 90.21 270 bottom
R3311  100KR2F-L1-GP  [R402H16]  33.02 87.29 270 bottom
R3401  10KR2J-3-GP  [R402H16]  34.77 57.3 270 bottom
R3402  10KR2J-3-GP  [R402H16]  31.1 58.47 270 top
R3403  10KR2J-3-GP  [R402H16]  31.69 55.34 0 bottom
R3404  100KR2J-1-GP  [R402H16]  31.49 56.3 90 top
R4002  20KR2F-L-GP  [R402H16]  124.69 44.52 270 bottom
R4003  100KR2F-L3-GP  [R402H16]  135.14 44.93 90 bottom
R4004  1KR2J-1-GP  [R402H16]  162.58 22.1 90 bottom
R4005  60D4R2F-3-GP  [R402H16]  162.57 23.13 90 bottom
R4006  0R2J-2-GP  [R402H16]  186.63 14.34 90 bottom
R4011  10KR2J-3-GP  [R402H16]  215.59 6.67 180 bottom
R4012  1KR2J-1-GP  [R402H16]  222.73 7 0 bottom
R4013  10KR2J-3-GP  [R402H16]  126.23 18.83 270 bottom
R4014  0R0402-PAD-2-GP  [0R0402-PAD-1]  221.23 6.36 270 bottom
R4016  0R0402-PAD-1-GP  [0R0402-PAD]  193.45 14.55 270 bottom
R4018  0R0402-PAD-2-GP  [0R0402-PAD-1]  202.52 77.06 270 bottom
R4020  10KR2J-3-GP  [R402H16]  202.48 78.22 90 bottom
R4022  0R2J-2-GP  [R402H16]  203.98 77.5 180 bottom
R4026  10KR2J-3-GP  [R402H16]  129.13 19.17 90 bottom
R4027  10KR2J-3-GP  [R402H16]  126.91 24.87 180 bottom
R4033  10KR2J-3-GP  [R402H16]  223.24 5.5 270 bottom
R4034  0R2J-2-GP  [R402H16]  155.66 21.94 270 bottom
R4035  0R0402-PAD-2-GP  [0R0402-PAD-1]  44.8 83.31 180 top
R4036  1KR2J-L2-GP  [R402H15]  129.18 45.42 0 bottom
R4037  0R0402-PAD-1-GP  [0R0402-PAD]  130.44 46.94 90 bottom
R4038  100KR2F-L3-GP  [R402H16]  126.17 42.82 180 bottom
R4044  1KR2J-1-GP  [R402H16]  131.49 22.36 270 bottom
R4045  0R2J-2-GP  [R402H16]  205.43 77.06 90 bottom
R4047  0R0402-PAD-2-GP  [0R0402-PAD-1]  187.94 11.06 180 bottom
R4051  0R0402-PAD-2-GP  [0R0402-PAD-1]  157.05 46 90 bottom
R4052  100KR2J-1-GP  [R402H16]  150.38 33.52 0 top
R4053  100KR2J-1-GP  [R402H16]  143.57 32.95 0 top
R4054  0R0402-PAD-2-GP  [0R0402-PAD-1]  153.64 13.91 180 bottom
R4057  100KR2J-1-GP  [R402H16]  149.15 31.6 180 top
R4318  2D2R2J-GP  [R402H16]  92.53 33.1 0 top
R4319  0R2J-2-GP  [R402H16]  84.41 32.81 0 top
R4320  100KR2F-L1-GP  [R402H16]  85.92 32.83 270 top
R4321  150KR2F-L-GP  [R402H16]  82.84 33.46 270 top
R4322  0R2J-2-GP  [R402H16]  82.84 32.34 270 top
R4324  1R2F-GP  [R402H16]  90.91 33.53 270 top
R4325  1R2F-GP  [R402H16]  85.92 33.86 90 top
R4326  10KR2J-3-GP  [R402H16]  77.85 57.76 0 bottom
R4327  69K8R2F-GP  [R402H16]  82.98 49.38 0 bottom
R4331  10KR2J-3-GP  [R402H16]  80.25 53.07 180 bottom
R4332  0R2J-2-GP  [R402H16]  81.94 49.38 0 bottom
R4501  10KR2J-3-GP  [R402H16]  104.14 79.37 0 top
R4502  4K7R2J-2-GP  [R402H16]  98.22 75.92 270 bottom
R4601  0R2J-2-GP  [R402H16]  111.09 44.35 180 top
R4602  0R0402-PAD-2-GP  [0R0402-PAD-1]  114.07 54.79 270 top
R4603  0R0402-PAD-2-GP  [0R0402-PAD-1]  125.96 54.86 90 top
R4604  0R0402-PAD-2-GP  [0R0402-PAD-1]  125.39 56.97 90 top
R5206  0R2J-2-GP  [R402H16]  120.8 17.81 270 bottom
R5301  1KR2J-1-GP  [R402H16]  16.32 75.23 90 top
R5305  0R2J-2-GP  [R402H16]  135.98 31.8 180 top
R5502  0R1206-PAD-1-GP  [0R1206-PAD-1]  22.08 35.2 270 top
R5503  0R0603-PAD-2-GP-U  [0R0603-PAD-1-U]  26.32 18.42 90 bottom
R5504  1KR2J-1-GP  [R402H16]  28.89 15.61 0 bottom
R5505  20KR2J-L2-GP  [R402H16]  27.84 17.91 270 top
R5506  10R2F-L-GP  [R402H14]  23.72 30.52 270 top
R5507  10KR2F-2-GP  [R402H16]  13.15 29.49 270 top
R5508  100R2F-L1-GP-U  [R402H14]  13.15 30.7 270 top
R5509  1KR2J-1-GP  [R402H16]  27.65 16.83 90 top
R5510  100R2J-2-GP  [R402H14]  23.06 32.91 0 top
R5511  10KR2F-2-GP  [R402H16]  22.03 32.91 180 top
R5512  100R2J-2-GP  [R402H14]  28.35 24.83 90 top
R5513  1KR2F-3-GP  [R402H16]  16.57 34.21 180 top
R5514  100KR2F-L1-GP  [R402H16]  14.27 34.24 180 top
R5515  300KR2F-GP  [R402H16]  21 32.91 180 top
R5518  10KR2F-2-GP  [R402H16]  23 25.42 270 top
R5519  10KR2F-2-GP  [R402H16]  24.9 25.49 90 top
R5521  300KR2F-GP  [R402H16]  23.73 28.55 90 top
R5522  10KR2J-3-GP  [R402H16]  12.01 9.88 0 top
R5523  10KR2J-3-GP  [R402H16]  13.05 9.88 0 top
R5524  10KR2J-3-GP  [R402H16]  14.17 9.89 0 top
R5531  0R2J-2-GP  [R402H16]  34.67 14.45 270 bottom
R5532  1R5J-2-GP  [R805H24]  11.8 17.34 0 bottom
R5533  0R0805-PAD-2-GP-U  [0R0805-PAD-1-U]  9.19 20.21 90 top
R5535  200R5J-GP  [R805H24]  17.42 22.35 180 top
R5536  0R0402-PAD-2-GP  [0R0402-PAD-1]  62.65 20.8 90 bottom
R5537  0R2J-2-GP  [R402H16]  64.12 23.14 180 bottom
R5538  D33R6F-GP  [R1206H26]  13.04 22.79 180 top
R5539  D33R6F-GP  [R1206H26]  15.28 22.79 180 top
R5601  0R0402-PAD-2-GP  [0R0402-PAD-1]  29.11 27.93 90 bottom
R5602  100KR2J-1-GP  [R402H16]  37.46 14.11 90 bottom
R5606  12KR2F-L-GP  [R402H16]  31.46 17.58 180 bottom
R5607  0R0402-PAD-2-GP  [0R0402-PAD-1]  30.5 23.06 0 top
R5608  0R2J-2-GP  [R402H16]  29.82 20.91 90 bottom
R5609  0R2J-2-GP  [R402H16]  28.82 21.95 90 bottom
R5610  4K7R2J-2-GP  [R402H16]  42.96 21.71 270 bottom
R5611  4K7R2J-2-GP  [R402H16]  37.89 22.73 0 top
R5612  4K7R2J-2-GP  [R402H16]  40.3 21.59 180 bottom
R5613  4K7R2J-2-GP  [R402H16]  47.65 11.53 0 bottom
R5614  4K7R2J-2-GP  [R402H16]  47.29 16.78 90 bottom
R5615  0R2J-2-GP  [R402H16]  48.11 12.99 270 bottom
R5616  0R2J-2-GP  [R402H16]  47.3 15.66 270 bottom
R5617  4K7R2J-2-GP  [R402H16]  38.03 20.19 270 top
R5618  4K7R2J-2-GP  [R402H16]  40.27 20.14 270 bottom
R5619  100KR2J-L-GP  [R402H16]  30.08 24.47 180 bottom
R5620  100KR2J-L-GP  [R402H16]  29.1 26.89 90 bottom
R5622  100KR2J-L-GP  [R402H16]  29.05 24.47 180 bottom
R5623  100KR2J-L-GP  [R402H16]  44.87 21.71 90 bottom
R5624  100KR2J-1-GP  [R402H16]  39.48 14.1 270 bottom
R5625  0R0402-PAD-2-GP  [0R0402-PAD-1]  50.18 19.92 0 bottom
R5626  0R0402-PAD-2-GP  [0R0402-PAD-1]  28.82 22.99 90 bottom
R5627  1KR2J-1-GP  [R402H16]  38.9 16.32 270 bottom
R5701  470R2F-GP  [R402H16]  63.32 26.31 0 top
R5702  470R2F-GP  [R402H16]  63.33 28.22 180 top
R5703  470R2F-GP  [R402H16]  63.32 23.77 180 top
R5706  470R2F-GP  [R402H16]  63.32 21.86 0 top
R5707  470R2F-GP  [R402H16]  62.18 25.93 180 top
R5708  470R2F-GP  [R402H16]  62.18 24.02 0 top
R5709  470R2F-GP  [R402H16]  62.31 28.35 0 top
R5710  470R2F-GP  [R402H16]  62.3 30.24 180 top
R5711  180R2J-1-GP  [R402H16]  57.57 25.68 180 top
R5712  180R2J-1-GP  [R402H16]  57.57 23.48 180 top
R5713  180R2J-1-GP  [R402H16]  57.57 27.79 180 top
R5715  180R2J-1-GP  [R402H16]  57.57 29.9 180 top
R5720  0R0805-PAD-2-GP-U  [0R0805-PAD-1-U]  59.39 52.14 0 top
R5721  2K2R2J-2-GP  [R402H16]  46.85 53.3 270 bottom
R5722  2K2R2J-2-GP  [R402H16]  45.75 59.41 90 bottom
R5730  100KR2J-1-GP  [R402H16]  44.22 59.82 0 bottom
R5731  0R0402-PAD-2-GP  [0R0402-PAD-1]  54.62 53.88 0 top
R5732  1MR2J-1-GP  [R402H16]  48.73 54.62 180 bottom
R6103  0R2J-2-GP  [R402H16]  133.47 7.74 90 top
R6104  0R2J-2-GP  [R402H16]  133.38 9.72 90 top
R6105  0R0402-PAD-2-GP  [0R0402-PAD-1]  147.37 14.6 180 bottom
R6107  0R0402-PAD-2-GP  [0R0402-PAD-1]  148.84 13.13 90 bottom
R6108  33R2J-2-GP  [R402H16]  132.69 14.11 90 top
R6109  0R0402-PAD-2-GP  [0R0402-PAD-1]  139.22 20.46 0 bottom
R6110  0R0402-PAD-2-GP  [0R0402-PAD-1]  140.24 20.46 0 bottom
R6111  0R2J-2-GP  [R402H16]  148.84 14.16 270 bottom
R6112  10KR2J-3-GP  [R402H16]  145.81 14.15 90 bottom
R6119  71K5R2F-1-GP  [R402H16]  132.6 18.72 90 top
R6120  100KR2F-L2-GP  [R402H16]  133.92 11.53 90 top
R6131  22R2J-L1-GP  [R402H16]  132.62 17.68 90 top
R6132  22R2J-L1-GP  [R402H16]  132.54 15.46 90 top
R6133  0R0402-PAD-2-GP  [0R0402-PAD-1]  131.39 11.67 180 top
R6134  0R0402-PAD-2-GP  [0R0402-PAD-1]  132.43 11.67 180 top
R6141  0R0402-PAD-2-GP  [0R0402-PAD-1]  138.52 14.56 0 bottom
R6160  10KR2J-3-GP  [R402H16]  130.36 14.64 270 top
R6301  0R2J-2-GP  [R402H16]  83.35 68.96 90 top
R6302  0R0402-PAD-2-GP  [0R0402-PAD-1]  85.24 69.98 90 top
R6303  0R0402-PAD-2-GP  [0R0402-PAD-1]  84.81 71.44 0 top
R6305  10KR2J-3-GP  [R402H16]  84.2 65.28 0 top
R6308  10KR2J-3-GP  [R402H16]  83.14 65.28 0 top
R6309  0R2J-2-GP  [R402H16]  83.35 67.92 90 top
R6310  10KR2J-3-GP  [R402H16]  84.92 67.47 180 top
R6311  0R0402-PAD-2-GP  [0R0402-PAD-1]  85.96 65.07 270 top
R6313  0R0402-PAD-2-GP  [0R0402-PAD-1]  91.39 66.04 90 bottom
R6314  0R0402-PAD-2-GP  [0R0402-PAD-1]  91.39 67.08 90 bottom
R6320  0R2J-2-GP  [R402H16]  82.1 73.01 90 top
R6402  10KR2J-3-GP  [R402H16]  123.63 8.71 270 top
R6403  10KR2J-3-GP  [R402H16]  121.81 16.22 180 bottom
R6404  300R5J-GP  [R805H24]  115.3 9.02 180 top
R6405  2K2R2J-2-GP  [R402H16]  121.74 8.38 90 top
R6407  150R5J-GP  [R805H24]  118.08 8.33 270 top
R6408  4K7R2J-2-GP  [R402H16]  125.54 8.27 270 top
R6409  75R2J-1-GP  [R402H16]  126.18 7.11 90 top
R6410  10KR2J-3-GP  [R402H16]  116.14 15.62 90 top
R6411  0R3J-0-U-GP  [R603H22]  111.55 4.38 270 top
R6412  0R0603-PAD-2-GP-U  [0R0603-PAD-1-U]  111.55 5.56 90 top
R6801  0R2J-L-GP  [R402H15]  98.39 8.47 90 top
R6802  150R2F-1-GP  [R402H16]  9.7 87.79 90 top
R6806  150R2F-1-GP  [R402H16]  9.15 83.99 90 top
R6807  150R2F-1-GP  [R402H16]  9.66 90.52 90 top
R6810  0R2J-L-GP  [R402H15]  103.56 18.86 180 bottom
R10013  0R0402-PAD-2-GP  [0R0402-PAD-1]  59.41 88.93 180 bottom
R10014  0R0402-PAD-2-GP  [0R0402-PAD-1]  58.37 88.93 180 bottom
R10021  0R0402-PAD-2-GP  [0R0402-PAD-1]  59.49 70.36 90 top
R24001  10KR2J-3-GP  [R402H16]  83.22 20.66 180 bottom
R24002  43R2F-2-GP  [R402H15]  92.31 18.8 270 top
R24003  6K49R2F-1-GP  [R402H16]  78.01 30.17 180 top
R24004  0R0402-PAD-2-GP  [0R0402-PAD-1]  93.91 21.84 180 bottom
R24005  0R2J-2-GP  [R402H16]  79.88 5.87 180 top
